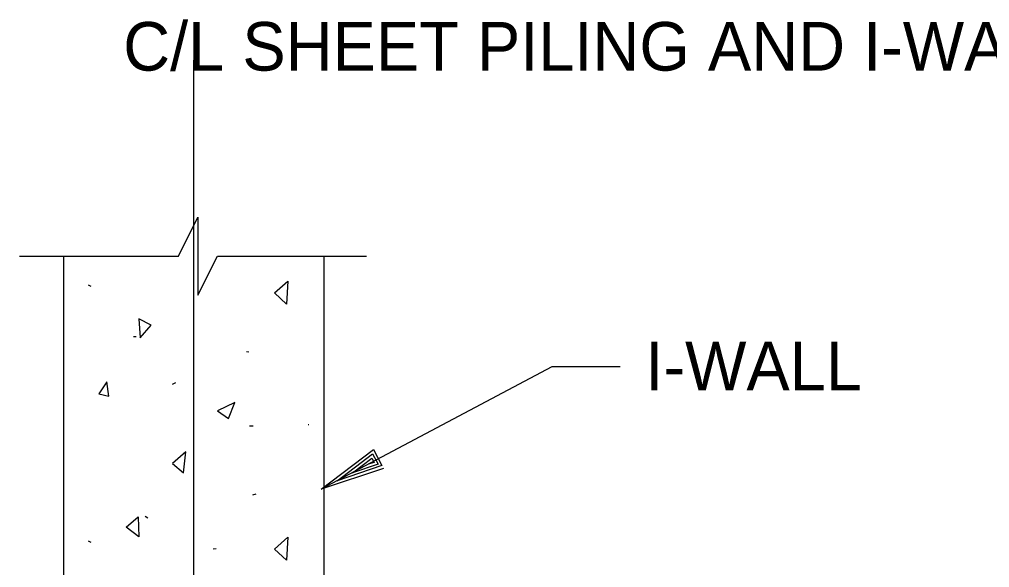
# Model space of a CAD drawing. Extents: x 22339.2 to 22413.4, y 22369.6 to 22418.8.
# Drawn here: x 22345.282 to 22349.01, y 22400.659 to 22402.763 of the extents above; entities that cross this region are included whole.
import ezdxf

# ---------------------------------------------------------------- set-up
doc = ezdxf.new("R2010")
doc.units = 0
for name, color, linetype in [('Level 1', 7, 'Continuous'), ('Level 2', 7, 'Continuous'), ('Level 4', 7, 'Continuous'), ('Level 44', 7, 'Continuous'), ('Level 7', 7, 'Continuous'), ('Level 8', 7, 'Continuous')]:
    doc.layers.add(name, color=color, linetype=linetype)

msp = doc.modelspace()

# ---------------------------------------------------------------- linework, layer by layer
at = {"layer": 'Level 1'}
for p, q in [((22345.9524, 22393.1147), (22345.9524, 22402.6063)), ((22345.2815, 22401.8542), (22345.8925, 22401.8542)), ((22346.0425, 22401.8542), (22346.6154, 22401.8542))]:
    msp.add_line(p, q, dxfattribs=at)
at = {"layer": 'Level 2'}
for points in [[(22347.5899, 22401.4297), (22347.3276, 22401.4297), (22346.441, 22400.9591)], [(22346.6807, 22401.0395), (22346.441, 22400.9591), (22346.6419, 22401.1125), (22346.675, 22401.0501), (22346.5023, 22400.9916), (22346.6387, 22401.0957), (22346.66, 22401.0557), (22346.5612, 22401.0228), (22346.6355, 22401.0789), (22346.6443, 22401.0625), (22346.6224, 22401.0554)]]:
    msp.add_lwpolyline(points, dxfattribs=at)
at = {"layer": 'Level 44'}
for p, q in [((22345.5578, 22401.7384), (22345.5471, 22401.7434)), ((22345.7306, 22401.5442), (22345.7206, 22401.5449)), ((22346.1638, 22401.4857), (22346.1538, 22401.4874)), ((22345.8808, 22401.3679), (22345.8688, 22401.3619)), ((22346.1798, 22401.2019), (22346.1663, 22401.2019)), ((22346.3933, 22401.2067), (22346.3911, 22401.2067)), ((22346.1906, 22400.9402), (22346.1771, 22400.9364)), ((22345.7756, 22400.8477), (22345.7643, 22400.8544)), ((22345.5578, 22400.7547), (22345.5471, 22400.7597)), ((22346.0376, 22400.7307), (22346.0266, 22400.7297))]:
    msp.add_line(p, q, dxfattribs=at)
for points in [[(22346.3078, 22401.6704), (22346.2616, 22401.7132), (22346.3128, 22401.7589)], [(22345.7451, 22401.5407), (22345.7878, 22401.5887), (22345.7401, 22401.6142)], [(22345.6248, 22401.3172), (22345.6178, 22401.3719), (22345.5871, 22401.3262)], [(22346.0853, 22401.2312), (22346.1091, 22401.2924), (22346.0428, 22401.2602)], [(22345.9213, 22401.1029), (22345.8701, 22401.0582), (22345.9126, 22401.0224)], [(22345.7401, 22400.7769), (22345.6921, 22400.8132), (22345.7381, 22400.8539)], [(22346.3078, 22400.6867), (22346.2616, 22400.7294), (22346.3128, 22400.7752)]]:
    msp.add_lwpolyline(points, close=True, dxfattribs=at)
at = {"layer": 'Level 7'}
for p, q in [((22345.4524, 22399.9781), (22345.4524, 22401.8542)), ((22346.4524, 22399.9781), (22346.4524, 22401.8542))]:
    msp.add_line(p, q, dxfattribs=at)
at = {"layer": 'Level 8'}
for p, q in [((22346.441, 22400.9591), (22346.441, 22400.9591)), ((22346.5023, 22400.9916), (22346.5023, 22400.9916))]:
    msp.add_line(p, q, dxfattribs=at)
msp.add_lwpolyline([(22345.8925, 22401.8542), (22345.967, 22402.0042), (22345.967, 22401.7046), (22346.0425, 22401.8542)], dxfattribs=at)

# ---------------------------------------------------------------- texts
at = {"layer": 'Level 4'}
for s, height, p in [('C/L SHEET PILING AND I-WALL', 0.186667, (22345.6805, 22402.5667)), ('I-WALL', 0.18667, (22347.6874, 22401.3388))]:
    msp.add_text(s, height=height, dxfattribs=at).set_placement(p)

doc.saveas('drawing.dxf')
